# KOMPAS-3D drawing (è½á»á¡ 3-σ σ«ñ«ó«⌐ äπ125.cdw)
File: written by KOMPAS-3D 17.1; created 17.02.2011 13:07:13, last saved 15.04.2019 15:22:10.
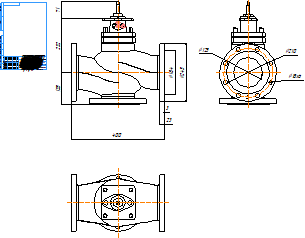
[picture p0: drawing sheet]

Title block, sheet 1: name: Клапан 3-х ходовой Ду125; material: Внимание! Данный продукт является объектом авторского права ООО «Торговый Дом АДЛ». / Запрещается изменение, копирование, распространение / (в том числе путем копирования на другие сайты и ресурсы в Интернете) / или любое иное использование информации и объектов без предварительного / согласия правообладателя (ООО «Торговый Дом АДЛ»).; scale: 1:1; sheets: 1; organisation: ООО "Торговый дом АДЛ"; sheet format: A4; stored path: \\adlc.lan\data\АДЛ_ПКД\3D-модели\ADL production\Клапаны ГРАНРЕГ\Трёхходовой клапан КМ307Ф\KOMPAS 2D\Клапан 3-х ходовой Ду125.cdw

Views: Спереди 1, Проекционный вид 2, Проекционный вид 3
Dimensions and other numbers on the sheet: 232; 135; 400; 71; 125; 210; 18; 3; 23; 184; 245; 1:1; 1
